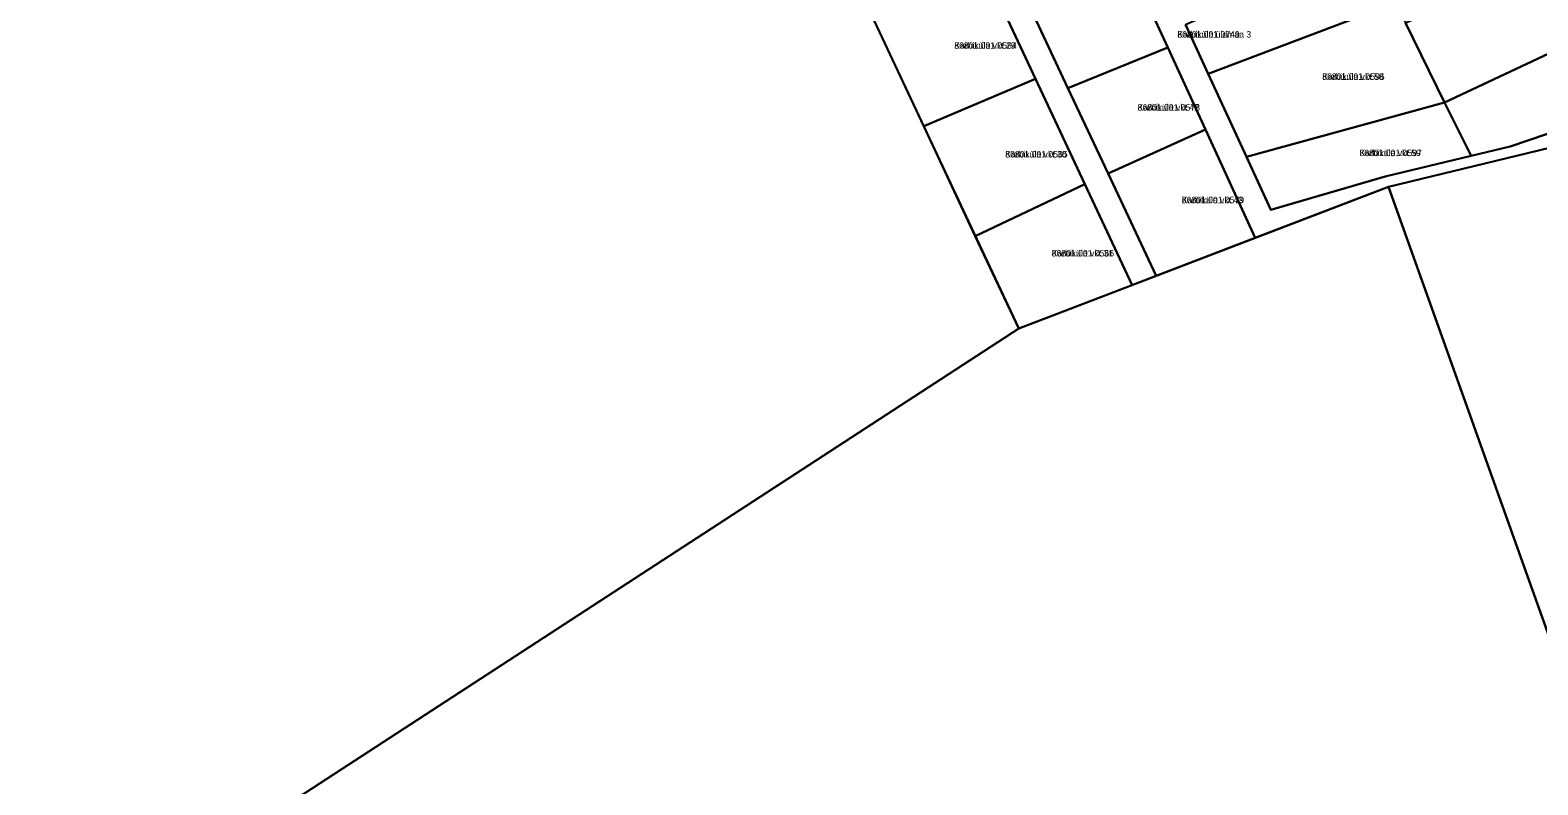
# Model space of a CAD drawing. Extents: x 484607 to 525396, y 6554521 to 6586559.
# Drawn here: x 516796.7 to 517147.5, y 6565115.8 to 6565291.3 of the extents above; entities that cross this region are included whole.
import ezdxf

# ---------------------------------------------------------------- set-up
doc = ezdxf.new("R2010")
doc.units = 0
for name, color, linetype in [('L_AADRESS', 7, 'Continuous'), ('PIIR', 7, 'Continuous'), ('TUNNUS', 7, 'Continuous')]:
    doc.layers.add(name, color=color, linetype=linetype)

msp = doc.modelspace()

# ---------------------------------------------------------------- linework, layer by layer
at = {"layer": 'PIIR'}
for points in [[(516875.31, 6565430.66), (516891.78, 6565403.85), (516957.63, 6565326.08), (516977.18, 6565327.34), (517026.74, 6565221.86), (516558.37, 6564917.18), (516499.43, 6565116.04)], [(517065.56, 6565292.58), (517107.88, 6565311.13), (517114.44, 6565297.64), (517070.83, 6565281.12)], [(517116.74, 6565292.98), (517154.68, 6565309.84), (517162.82, 6565291.83), (517125.83, 6565274.49)], [(516992.53, 6565294.66), (517018.92, 6565305.01), (517030.63, 6565279.98), (517004.63, 6565268.92)], [(517029.7, 6565295.88), (517053.19, 6565305.08), (517061.41, 6565287.23), (517038.18, 6565277.82)], [(517070.83, 6565281.12), (517114.44, 6565297.64), (517116.74, 6565292.98), (517125.83, 6565274.49), (517079.71, 6565261.82)], [(517125.83, 6565274.49), (517162.82, 6565291.83), (517170.74, 6565274.29), (517141.07, 6565264.25), (517131.98, 6565262.06)], [(517038.18, 6565277.82), (517061.41, 6565287.23), (517070.18, 6565268.18), (517047.53, 6565257.91)], [(517335.42, 6564763.06), (517333.4, 6564759.01), (517329.14, 6564753.22), (517323.96, 6564748.34), (517311.07, 6564747.43), (517304.39, 6564746.53), (517299.38, 6564743.14), (517296.6, 6564740.13), (517292.22, 6564752.38), (517112.75, 6565254.83), (517172.94, 6565269.42), (517247.1, 6565287.39), (517343.63, 6564795.47), (517345, 6564788.57), (517343.38, 6564788.24), (517341.9, 6564785.71), (517340.48, 6564778.56), (517338.13, 6564770.33)], [(517004.63, 6565268.92), (517030.63, 6565279.98), (517042.1, 6565255.44), (517016.64, 6565243.36)], [(517079.71, 6565261.82), (517125.83, 6565274.49), (517131.98, 6565262.06), (517112, 6565257.22), (517085.38, 6565249.49)], [(517047.53, 6565257.91), (517070.18, 6565268.18), (517081.78, 6565242.96), (517058.71, 6565234.11)], [(517016.64, 6565243.36), (517042.1, 6565255.44), (517053.09, 6565231.96), (517026.74, 6565221.86)]]:
    msp.add_lwpolyline(points, close=True, dxfattribs=at)
for points in [[(517029.7, 6565295.88), (517038.18, 6565277.82), (517047.53, 6565257.91), (517058.71, 6565234.11), (517053.09, 6565231.96), (517042.1, 6565255.44), (517030.63, 6565279.98), (517018.92, 6565305.01)], [(517172.94, 6565269.42), (517112.75, 6565254.83), (517081.78, 6565242.96), (517070.18, 6565268.18), (517061.41, 6565287.23), (517053.19, 6565305.08)], [(517065.56, 6565292.58), (517070.83, 6565281.12), (517079.71, 6565261.82), (517085.38, 6565249.49), (517112, 6565257.22), (517131.98, 6565262.06), (517141.07, 6565264.25), (517170.74, 6565274.29)], [(516558.37, 6564917.18), (517026.74, 6565221.86), (517112.75, 6565254.83), (517292.22, 6564752.38)]]:
    msp.add_lwpolyline(points, dxfattribs=at)

# ---------------------------------------------------------------- texts
at = {"layer": 'L_AADRESS'}
for s, p in [('Karbiküla üldmaa 3', (517063.64, 6565289.56)), ('Karbiküla vkt 29', (517011.75, 6565286.97)), ('Karbiküla vkt 58', (517097.36, 6565279.73)), ('Karbiküla vkt 42', (517054.4, 6565272.57)), ('Karbiküla vkt 30', (517023.61, 6565261.67)), ('Karbiküla vkt 59', (517106.01, 6565261.99)), ('Karbiküla vkt 43', (517064.66, 6565251.03)), ('Karbiküla vkt 31', (517034.41, 6565238.65))]:
    msp.add_text(s, height=1.5, dxfattribs=at).set_placement(p)
at = {"layer": 'TUNNUS'}
for s, p in [('86801:001:0749', (517063.64, 6565289.56)), ('86801:001:0564', (517011.75, 6565286.97)), ('86801:001:0596', (517097.36, 6565279.73)), ('86801:001:0578', (517054.4, 6565272.57)), ('86801:001:0565', (517023.61, 6565261.67)), ('86801:001:0597', (517106.01, 6565261.99)), ('86801:001:0579', (517064.66, 6565251.03)), ('86801:001:0566', (517034.41, 6565238.65))]:
    msp.add_text(s, height=1.5, dxfattribs=at).set_placement(p)

doc.saveas('drawing.dxf')
